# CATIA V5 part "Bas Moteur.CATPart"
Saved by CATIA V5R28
Part number: Bas moteur - pièce de référence
Bounding box of the stored display mesh (mm): x -20 to 52, y -22 to 22, z -22 to 49
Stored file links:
  D:\Back up\Mission d'enseignement\TP Catia\2 oct - Assemblage\Bas Moteur.CATPart
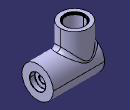
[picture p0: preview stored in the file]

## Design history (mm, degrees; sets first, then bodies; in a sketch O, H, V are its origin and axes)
Body1 (main body)
  Sketch1 on yz-plane, origin (0, 0, 0), H (0, 1, 0), V (0, 0, 1)
    circle A1 centre (0, 0) radius 22
    circle A2 centre (0, 0) radius 16
    radius A1 = 22
    radius A2 = 16
  Pad1: profile Sketch1, direction (1, 0, 0), length 20, mirrored extent
  Sketch2 on end face of Pad1, origin (20, 0, 0), H (0, 1, 0), V (0, 0, 1)
    circle A1 centre (0, 0) radius 22
    reference projected circle E1 centre (0, 0) radius 22 from edge [face of Pad1 from Sketch1.A1 | end face of Pad1]
    circle A2 centre (0, 0) radius 7.5
    radius A2 = 7.5
    equal size: A1 E1
  Pad2: profile Sketch2, direction (1, 0, 0), length 15
  Sketch3 on end face of Pad2, origin (35, 0, 0), H (0, 1, 0), V (0, 0, 1)
    circle A1 centre (0, 0) radius 22
    circle A2 centre (0, 0) radius 5
    reference projected circle E1 centre (0, 0) radius 22 from edge [face of Pad2 | end face of Pad2]
    reference projected circle E2 centre (0, 0) radius 22 from edge [face of Pad2 | end face of Pad2]
    radius A2 = 5
    concentricity: A1 E1
    equal size: A1 E2
  Pad3: profile Sketch3, direction (1, 0, 0), length 10
  Sketch4 on end face of Pad3, origin (45, 0, 0), H (0, 1, 0), V (0, 0, 1)
    circle A1 centre (0, 0) radius 22
    circle A2 centre (0, 0) radius 11
    reference projected circle E1 centre (0, 0) radius 22 from edge [face of Pad3 | end face of Pad3]
    radius A2 = 11
    equal size: A1 E1
  Pad4: profile Sketch4, direction (1, 0, 0), length 7
  Plane1: type Offset, RefPlane xy-plane, Offset 49
  Sketch5 on Plane1, origin (0, 0, 49), H (1, 0, 0), V (0, 1, 0)
    circle A1 centre (0, 0) radius 20
    radius A1 = 20
  Pad5: profile Sketch5, direction (0, 0, -1), up to face of Pad4
  Sketch6 on Plane1, origin (0, 0, 49), H (1, 0, 0), V (0, 1, 0)
    circle A1 centre (0, 0) radius 10.5
    radius A1 = 10.5
  Pocket1: profile Sketch6, direction (0, 0, -1), through (limit type 6)
  Sketch7 on Plane1, origin (0, 0, 49), H (1, 0, 0), V (0, 1, 0)
    circle A1 centre (0, 0) radius 12.5
    radius A1 = 12.5
  Pocket2: profile Sketch7, direction (0, 0, -1), length 28
  Sketch8 on Plane1, origin (0, 0, 49), H (1, 0, 0), V (0, 1, 0)
    circle A1 centre (0, 0) radius 14
    radius A1 = 14
  Pocket3: profile Sketch8, direction (0, 0, -1), length 1.5
  Chamfer1: length 0.5, angle 45, on edge [start face of Pad5 | face of Pocket3 from Sketch8.A1]; edge [face of Pocket3 from Sketch8.A1 | end face of Pocket3]; edge [end face of Pocket3 | face of Pocket2 from Sketch7.A1]; edge [end face of Pad4 | face of Pad4 from Sketch4.A2]; edge [face of Pad4 from Sketch4.A2 | end face of Pad3]; edge [end face of Pad3 | face of Pad3 from Sketch3.A2]
  Fillet1: radius 5, on edge [face of Pad5 from Sketch5.A1 | face of Pad4]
